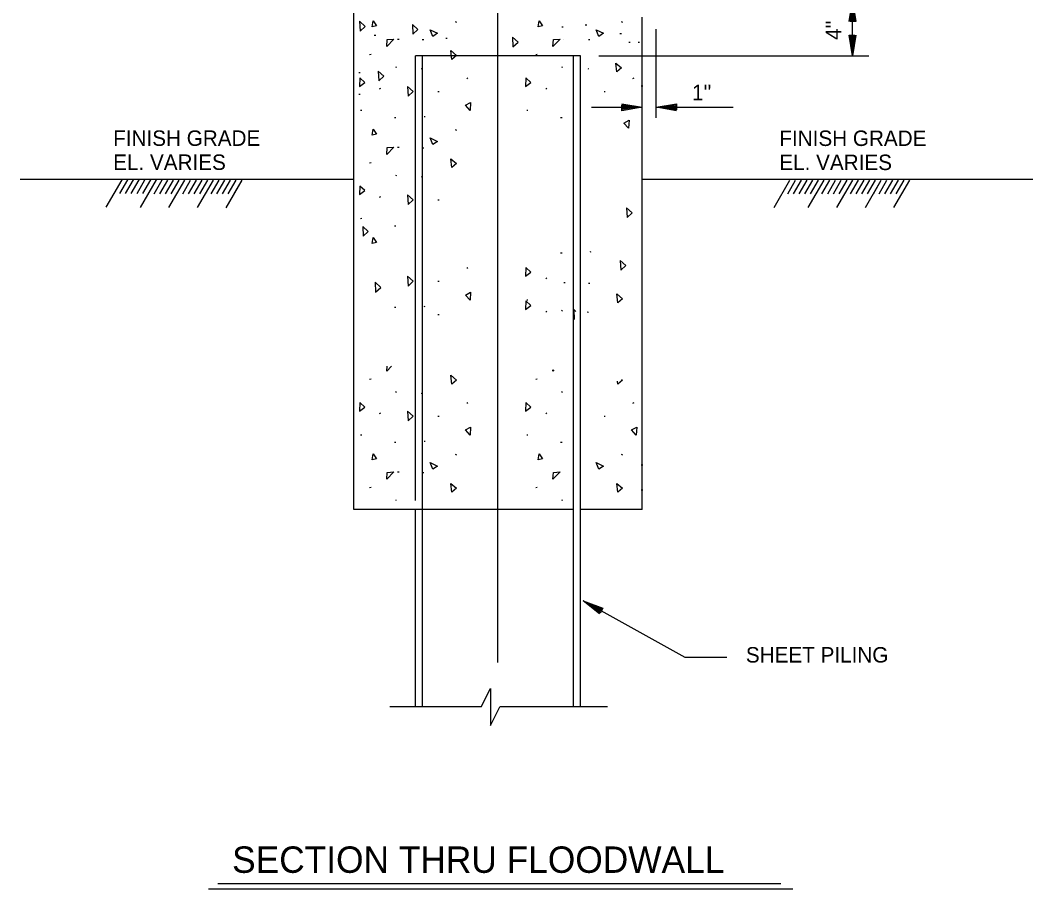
# Model space of a CAD drawing. Extents: x 22388.1 to 22405.7, y 22369.6 to 22390.4.
# Drawn here: x 22402.034 to 22405.103, y 22383.025 to 22385.656 of the extents above; entities that cross this region are included whole.
import ezdxf

# ---------------------------------------------------------------- set-up
doc = ezdxf.new("R2010")
doc.units = 0
for name, color, linetype in [('Level 1', 7, 'Continuous'), ('Level 10', 7, 'Continuous'), ('Level 2', 7, 'Continuous'), ('Level 3', 7, 'Continuous'), ('Level 4', 7, 'Continuous'), ('Level 44', 7, 'Continuous'), ('Level 7', 7, 'Continuous')]:
    doc.layers.add(name, color=color, linetype=linetype)

msp = doc.modelspace()

# ---------------------------------------------------------------- linework, layer by layer
at = {"layer": 'Level 1'}
for p, q in [((22403.482, 22383.7104), (22403.482, 22390.1172)), ((22404.5563, 22385.5486), (22404.5563, 22385.7153)), ((22403.9611, 22385.3605), (22403.9611, 22385.6289)), ((22403.7881, 22385.5486), (22404.6056, 22385.5486)), ((22403.7651, 22385.3927), (22403.9195, 22385.3927)), ((22403.9611, 22385.3927), (22404.1953, 22385.3927)), ((22402.2945, 22385.0898), (22402.343, 22385.1729)), ((22402.3361, 22385.1313), (22402.3603, 22385.1728)), ((22402.3534, 22385.1312), (22402.3776, 22385.1727)), ((22402.3707, 22385.1311), (22402.3949, 22385.1727)), ((22402.388, 22385.1311), (22402.4122, 22385.1726)), ((22402.3984, 22385.0894), (22402.4468, 22385.1725)), ((22402.4053, 22385.131), (22402.4295, 22385.1725)), ((22402.4399, 22385.1308), (22402.4641, 22385.1724)), ((22402.4572, 22385.1308), (22402.4814, 22385.1723)), ((22402.4745, 22385.1307), (22402.4987, 22385.1722)), ((22402.4849, 22385.089), (22402.5333, 22385.1721)), ((22402.4918, 22385.1306), (22402.516, 22385.1722)), ((22402.5091, 22385.1306), (22402.5333, 22385.1721)), ((22402.5264, 22385.1305), (22402.5506, 22385.172)), ((22402.5437, 22385.1304), (22402.5679, 22385.172)), ((22402.561, 22385.1304), (22402.5852, 22385.1719)), ((22402.5714, 22385.0887), (22402.6198, 22385.1718)), ((22402.5783, 22385.1303), (22402.6025, 22385.1718)), ((22402.5956, 22385.1302), (22402.6198, 22385.1718)), ((22402.613, 22385.1302), (22402.6371, 22385.1717)), ((22402.6303, 22385.1301), (22402.6545, 22385.1716)), ((22402.6475, 22385.13), (22402.6717, 22385.1716)), ((22402.6579, 22385.0884), (22402.7063, 22385.1714)), ((22402.6648, 22385.13), (22402.689, 22385.1715)), ((22402.6822, 22385.1299), (22402.7063, 22385.1714)), ((22404.3188, 22385.0887), (22404.3669, 22385.172)), ((22404.3602, 22385.1304), (22404.3842, 22385.172)), ((22404.3775, 22385.1304), (22404.4015, 22385.172)), ((22404.3948, 22385.1304), (22404.4188, 22385.172)), ((22404.4121, 22385.1303), (22404.4361, 22385.172)), ((22404.4226, 22385.0887), (22404.4707, 22385.172)), ((22404.4294, 22385.1303), (22404.4534, 22385.172)), ((22404.464, 22385.1303), (22404.488, 22385.172)), ((22404.4813, 22385.1303), (22404.5053, 22385.172)), ((22404.4986, 22385.1303), (22404.5226, 22385.172)), ((22404.5092, 22385.0887), (22404.5572, 22385.1719)), ((22404.5159, 22385.1303), (22404.5399, 22385.1719)), ((22404.5332, 22385.1303), (22404.5572, 22385.1719)), ((22404.5505, 22385.1303), (22404.5745, 22385.1719)), ((22404.5678, 22385.1303), (22404.5918, 22385.1719)), ((22404.5851, 22385.1303), (22404.6091, 22385.1719)), ((22404.5957, 22385.0887), (22404.6437, 22385.1719)), ((22404.6024, 22385.1303), (22404.6264, 22385.1719)), ((22404.6197, 22385.1303), (22404.6437, 22385.1719)), ((22404.637, 22385.1303), (22404.661, 22385.1719)), ((22404.6543, 22385.1303), (22404.6784, 22385.1719)), ((22404.6716, 22385.1303), (22404.6956, 22385.1719)), ((22404.6822, 22385.0887), (22404.7303, 22385.1719)), ((22404.6889, 22385.1303), (22404.713, 22385.1719)), ((22404.7063, 22385.1303), (22404.7303, 22385.1719)), ((22403.4314, 22383.5756), (22403.1539, 22383.5756)), ((22403.8137, 22383.5756), (22403.4876, 22383.5756))]:
    msp.add_line(p, q, dxfattribs=at)
msp.add_lwpolyline([(22403.4314, 22383.5756), (22403.4593, 22383.6319), (22403.4593, 22383.5195), (22403.4876, 22383.5756)], dxfattribs=at)
at = {"layer": 'Level 10'}
for p, q in [((22403.0451, 22385.1736), (22402.0341, 22385.1736)), ((22405.1028, 22385.1736), (22403.9195, 22385.1736)), ((22402.6042, 22383.0248), (22404.3761, 22383.0248)), ((22402.633, 22383.0406), (22404.3394, 22383.0406))]:
    msp.add_line(p, q, dxfattribs=at)
at = {"layer": 'Level 2'}
for p, q in [((22403.232, 22384.2012), (22403.232, 22385.5486)), ((22403.732, 22385.5486), (22403.232, 22385.5486)), ((22403.2528, 22383.5756), (22403.2528, 22385.5486)), ((22403.7111, 22383.5756), (22403.7111, 22385.5486)), ((22403.732, 22383.5756), (22403.732, 22385.5486)), ((22404.5563, 22385.5659), (22404.5563, 22385.5659)), ((22404.5563, 22385.5486), (22404.5563, 22385.5486)), ((22403.9021, 22385.3927), (22403.9021, 22385.3927)), ((22403.9195, 22385.3927), (22403.9195, 22385.3927)), ((22403.9611, 22385.3927), (22403.9611, 22385.3927)), ((22403.9785, 22385.3927), (22403.9785, 22385.3927)), ((22403.232, 22383.5756), (22403.232, 22384.1736)), ((22403.7403, 22383.8967), (22403.7403, 22383.8967)), ((22403.7555, 22383.8883), (22403.7555, 22383.8883))]:
    msp.add_line(p, q, dxfattribs=at)
for points in [[(22404.546, 22385.6529), (22404.5563, 22385.7153), (22404.5667, 22385.6529), (22404.549, 22385.6529), (22404.5563, 22385.6979), (22404.5633, 22385.6556), (22404.552, 22385.6556), (22404.5563, 22385.6813), (22404.56, 22385.6583), (22404.5553, 22385.6583), (22404.5563, 22385.6639)], [(22404.5667, 22385.6109), (22404.5563, 22385.5486), (22404.546, 22385.6109), (22404.5637, 22385.6109), (22404.5563, 22385.5659), (22404.5493, 22385.6083), (22404.5607, 22385.6083), (22404.5563, 22385.5826), (22404.5527, 22385.6056), (22404.5573, 22385.6056), (22404.5563, 22385.5999)], [(22403.8571, 22385.403), (22403.9195, 22385.3927), (22403.8571, 22385.3823), (22403.8571, 22385.4), (22403.9021, 22385.3927), (22403.8598, 22385.3857), (22403.8598, 22385.397), (22403.8855, 22385.3927), (22403.8625, 22385.389), (22403.8625, 22385.3937), (22403.8681, 22385.3927)], [(22404.0235, 22385.3823), (22403.9611, 22385.3927), (22404.0235, 22385.403), (22404.0235, 22385.3853), (22403.9785, 22385.3927), (22404.0208, 22385.3997), (22404.0208, 22385.3883), (22403.9951, 22385.3927), (22404.0181, 22385.3963), (22404.0181, 22385.3917), (22404.0125, 22385.3927)], [(22404.1752, 22383.725), (22404.0493, 22383.725), (22403.7403, 22383.8967)], [(22403.7898, 22383.8574), (22403.7403, 22383.8967), (22403.7999, 22383.8754), (22403.7913, 22383.86), (22403.7555, 22383.8883), (22403.7959, 22383.8738), (22403.7904, 22383.8639), (22403.7701, 22383.8802), (22403.792, 22383.8722), (22403.7897, 22383.8681), (22403.7852, 22383.8717)]]:
    msp.add_lwpolyline(points, dxfattribs=at)
at = {"layer": 'Level 44'}
for p, q in [((22403.3523, 22385.653), (22403.3563, 22385.651)), ((22403.6751, 22385.6369), (22403.6796, 22385.6369)), ((22403.7468, 22385.6427), (22403.7513, 22385.6427)), ((22403.8556, 22385.653), (22403.8596, 22385.651)), ((22403.1073, 22385.611), (22403.1118, 22385.611)), ((22403.178, 22385.5993), (22403.1822, 22385.5993)), ((22403.3236, 22385.6016), (22403.3281, 22385.6016)), ((22403.6813, 22385.5993), (22403.6817, 22385.5993)), ((22403.8516, 22385.6157), (22403.8561, 22385.6157)), ((22403.2526, 22385.5977), (22403.2571, 22385.5977)), ((22403.756, 22385.5977), (22403.7605, 22385.5977)), ((22403.8786, 22385.5896), (22403.8831, 22385.5896)), ((22403.9068, 22385.5896), (22403.9113, 22385.5896)), ((22403.0931, 22385.5527), (22403.0975, 22385.5534)), ((22403.5965, 22385.5527), (22403.6008, 22385.5534)), ((22403.1714, 22385.5149), (22403.1746, 22385.5137)), ((22403.249, 22385.5104), (22403.2535, 22385.5092)), ((22403.6747, 22385.5149), (22403.678, 22385.5137)), ((22403.7541, 22385.5099), (22403.7569, 22385.5092)), ((22403.0602, 22385.498), (22403.0647, 22385.498)), ((22403.3874, 22385.4796), (22403.3911, 22385.4818)), ((22403.8907, 22385.4796), (22403.8945, 22385.4818)), ((22403.1233, 22385.4486), (22403.1269, 22385.4503)), ((22403.6266, 22385.4486), (22403.6302, 22385.4503)), ((22403.9162, 22385.4577), (22403.9207, 22385.4577)), ((22403.0602, 22385.4321), (22403.0647, 22385.4321)), ((22403.3, 22385.4406), (22403.3037, 22385.4403)), ((22403.8034, 22385.4406), (22403.8071, 22385.4403)), ((22403.0657, 22385.3838), (22403.069, 22385.3841)), ((22403.1683, 22385.3615), (22403.1728, 22385.3615)), ((22403.258, 22385.3643), (22403.2613, 22385.3649)), ((22403.5691, 22385.3838), (22403.5724, 22385.3841)), ((22403.6716, 22385.3615), (22403.6761, 22385.3615)), ((22403.3523, 22385.3251), (22403.3563, 22385.3231)), ((22403.178, 22385.2713), (22403.1822, 22385.2713)), ((22403.2526, 22385.2698), (22403.2571, 22385.2698)), ((22403.0931, 22385.2248), (22403.0975, 22385.2255)), ((22403.1714, 22385.187), (22403.1746, 22385.1858)), ((22403.249, 22385.1825), (22403.2535, 22385.1813)), ((22403.1233, 22385.1207), (22403.1269, 22385.1223)), ((22403.3, 22385.1127), (22403.3037, 22385.1123)), ((22403.0657, 22385.0559), (22403.069, 22385.0562)), ((22403.1683, 22385.0336), (22403.1728, 22385.0336)), ((22403.7613, 22384.9548), (22403.7646, 22384.9554)), ((22403.6716, 22384.952), (22403.6761, 22384.952)), ((22403.3874, 22384.9047), (22403.3911, 22384.907)), ((22403.3, 22384.8657), (22403.3037, 22384.8654)), ((22403.6266, 22384.8737), (22403.6302, 22384.8754)), ((22403.6813, 22384.8618), (22403.6856, 22384.8618)), ((22403.756, 22384.8602), (22403.7605, 22384.8602)), ((22403.5691, 22384.809), (22403.5724, 22384.8092)), ((22403.1683, 22384.7866), (22403.1728, 22384.7866)), ((22403.258, 22384.7895), (22403.2613, 22384.7901)), ((22403.6266, 22384.7728), (22403.6302, 22384.7745)), ((22403.6747, 22384.7775), (22403.678, 22384.7762)), ((22403.7524, 22384.773), (22403.7569, 22384.7717)), ((22403.3, 22384.7648), (22403.3037, 22384.7645)), ((22403.0931, 22384.5689), (22403.0975, 22384.5697)), ((22403.5965, 22384.5689), (22403.6008, 22384.5697)), ((22403.1714, 22384.5312), (22403.1746, 22384.5299)), ((22403.249, 22384.5267), (22403.2535, 22384.5254)), ((22403.6747, 22384.5312), (22403.678, 22384.5299)), ((22403.3874, 22384.4958), (22403.3911, 22384.4981)), ((22403.8907, 22384.4958), (22403.8945, 22384.4981)), ((22403.1233, 22384.4648), (22403.1269, 22384.4665)), ((22403.6266, 22384.4648), (22403.6302, 22384.4665)), ((22403.3, 22384.4568), (22403.3037, 22384.4565)), ((22403.8034, 22384.4568), (22403.8071, 22384.4565)), ((22403.0657, 22384.4001), (22403.069, 22384.4003)), ((22403.1683, 22384.3778), (22403.1728, 22384.3778)), ((22403.258, 22384.3806), (22403.2613, 22384.3812)), ((22403.5691, 22384.4001), (22403.5724, 22384.4003)), ((22403.6716, 22384.3778), (22403.6761, 22384.3778)), ((22403.3523, 22384.3413), (22403.3563, 22384.3393)), ((22403.8556, 22384.3413), (22403.8596, 22384.3393)), ((22403.178, 22384.2876), (22403.1822, 22384.2876)), ((22403.2526, 22384.286), (22403.2571, 22384.286)), ((22403.9162, 22384.3091), (22403.9207, 22384.3091)), ((22403.0931, 22384.241), (22403.0975, 22384.2418)), ((22403.5965, 22384.241), (22403.6008, 22384.2418)), ((22403.9162, 22384.2338), (22403.9207, 22384.2338)), ((22403.1714, 22384.2033), (22403.1731, 22384.2026)), ((22403.6747, 22384.2033), (22403.678, 22384.202))]:
    msp.add_line(p, q, dxfattribs=at)
for points in [[(22403.0643, 22385.6236), (22403.0797, 22385.6379), (22403.0626, 22385.6531)], [(22403.101, 22385.6361), (22403.1033, 22385.6543), (22403.1135, 22385.6391)], [(22403.2242, 22385.6142), (22403.2396, 22385.6285), (22403.2225, 22385.6437)], [(22403.6043, 22385.6361), (22403.6066, 22385.6543), (22403.6169, 22385.6391)], [(22403.1467, 22385.5982), (22403.1667, 22385.5993), (22403.145, 22385.5771)], [(22403.2841, 22385.6074), (22403.2762, 22385.6278), (22403.2983, 22385.6171)], [(22403.5274, 22385.5753), (22403.5428, 22385.5895), (22403.5257, 22385.6048)], [(22403.6501, 22385.5982), (22403.6701, 22385.5993), (22403.6484, 22385.5771)], [(22403.7875, 22385.6074), (22403.7796, 22385.6278), (22403.8016, 22385.6171)], [(22403.3388, 22385.5647), (22403.3559, 22385.5498), (22403.3417, 22385.5378)], [(22403.8396, 22385.5267), (22403.8567, 22385.5118), (22403.8425, 22385.4999)], [(22403.0625, 22385.456), (22403.0785, 22385.4681), (22403.0632, 22385.4817)], [(22403.1207, 22385.473), (22403.1361, 22385.4872), (22403.119, 22385.5025)], [(22403.5659, 22385.456), (22403.5819, 22385.4681), (22403.5666, 22385.4817)], [(22403.21, 22385.4259), (22403.2254, 22385.4402), (22403.2083, 22385.4554)], [(22403.3975, 22385.3827), (22403.3833, 22385.3987), (22403.3992, 22385.4072)], [(22403.8779, 22385.329), (22403.8636, 22385.345), (22403.8796, 22385.3535)], [(22403.101, 22385.3082), (22403.1033, 22385.3264), (22403.1135, 22385.3112)], [(22403.2841, 22385.2795), (22403.2762, 22385.2999), (22403.2983, 22385.2892)], [(22403.1467, 22385.2703), (22403.1667, 22385.2713), (22403.145, 22385.2492)], [(22403.3388, 22385.2368), (22403.3559, 22385.2218), (22403.3417, 22385.2099)], [(22403.0625, 22385.1281), (22403.0785, 22385.1402), (22403.0632, 22385.1538)], [(22403.21, 22385.098), (22403.2254, 22385.1123), (22403.2083, 22385.1275)], [(22403.8732, 22385.0587), (22403.8886, 22385.073), (22403.8715, 22385.0882)], [(22403.0737, 22385.0023), (22403.0891, 22385.0165), (22403.072, 22385.0318)], [(22403.101, 22384.9803), (22403.1033, 22384.9985), (22403.1135, 22384.9833)], [(22403.8544, 22384.8987), (22403.8698, 22384.913), (22403.8527, 22384.9282)], [(22403.5659, 22384.8812), (22403.5819, 22384.8932), (22403.5666, 22384.9068)], [(22403.21, 22384.8511), (22403.2254, 22384.8653), (22403.2083, 22384.8806)], [(22403.1113, 22384.8328), (22403.1267, 22384.847), (22403.1096, 22384.8623)], [(22403.3975, 22384.8078), (22403.3833, 22384.8238), (22403.3992, 22384.8323)], [(22403.5659, 22384.7802), (22403.5819, 22384.7923), (22403.5666, 22384.8059)], [(22403.8421, 22384.8272), (22403.8592, 22384.8123), (22403.845, 22384.8004)], [(22403.3388, 22384.5809), (22403.3559, 22384.566), (22403.3417, 22384.5541)], [(22403.0625, 22384.4723), (22403.0785, 22384.4843), (22403.0632, 22384.4979)], [(22403.5659, 22384.4723), (22403.5819, 22384.4843), (22403.5666, 22384.4979)], [(22403.21, 22384.4422), (22403.2254, 22384.4564), (22403.2083, 22384.4717)], [(22403.3975, 22384.3989), (22403.3833, 22384.4149), (22403.3992, 22384.4234)], [(22403.9009, 22384.3989), (22403.8866, 22384.4149), (22403.9025, 22384.4234)], [(22403.101, 22384.3244), (22403.1033, 22384.3427), (22403.1135, 22384.3274)], [(22403.6043, 22384.3244), (22403.6066, 22384.3427), (22403.6169, 22384.3274)], [(22403.2841, 22384.2958), (22403.2762, 22384.3162), (22403.2983, 22384.3054)], [(22403.7875, 22384.2958), (22403.7796, 22384.3162), (22403.8016, 22384.3054)], [(22403.1467, 22384.2865), (22403.1667, 22384.2876), (22403.145, 22384.2654)], [(22403.6501, 22384.2865), (22403.6701, 22384.2876), (22403.6484, 22384.2654)], [(22403.3388, 22384.253), (22403.3559, 22384.2381), (22403.3417, 22384.2262)], [(22403.8421, 22384.253), (22403.8592, 22384.2381), (22403.845, 22384.2262)]]:
    msp.add_lwpolyline(points, close=True, dxfattribs=at)
for points in [[(22403.7181, 22384.7738), (22403.7116, 22384.7796), (22403.7133, 22384.7501)], [(22403.1595, 22384.6081), (22403.145, 22384.5933), (22403.1462, 22384.6083)], [(22403.6518, 22384.5968), (22403.6484, 22384.5933), (22403.6486, 22384.5969)], [(22403.8566, 22384.5683), (22403.8592, 22384.566), (22403.845, 22384.5541), (22403.8441, 22384.5623)]]:
    msp.add_lwpolyline(points, dxfattribs=at)
at = {"layer": 'Level 7'}
for p, q in [((22403.0451, 22384.1736), (22403.0451, 22385.9242)), ((22403.9195, 22384.1736), (22403.9195, 22385.6658)), ((22403.7111, 22384.1736), (22403.0451, 22384.1736)), ((22403.9195, 22384.1736), (22403.732, 22384.1736))]:
    msp.add_line(p, q, dxfattribs=at)

# ---------------------------------------------------------------- texts
at = {"layer": 'Level 3'}
msp.add_text('SECTION THRU FLOODWALL', height=0.08, dxfattribs=at).set_placement((22402.6763, 22383.073))
at = {"layer": 'Level 4'}
msp.add_text("4''", height=0.04688, rotation=90, dxfattribs=at).set_placement((22404.5224, 22385.5967))
for s, height, p in [("1''", 0.04688, (22404.07, 22385.4139)), ('FINISH GRADE', 0.046875, (22402.3158, 22385.2757)), ('FINISH GRADE', 0.046875, (22404.3348, 22385.2754)), ('EL. VARIES', 0.04688, (22402.3158, 22385.2028)), ('EL. VARIES', 0.04688, (22404.3348, 22385.2024)), ('SHEET PILING', 0.046875, (22404.2334, 22383.7102))]:
    msp.add_text(s, height=height, dxfattribs=at).set_placement(p)

doc.saveas('drawing.dxf')
